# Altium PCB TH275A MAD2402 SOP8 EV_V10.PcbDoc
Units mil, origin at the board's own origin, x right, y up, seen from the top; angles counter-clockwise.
Board outline 1968.5 x 1181.1 mil, 2 copper layers (Top Layer, Bottom Layer); 56 components, 19 nets, 137 pads, 71 vias.
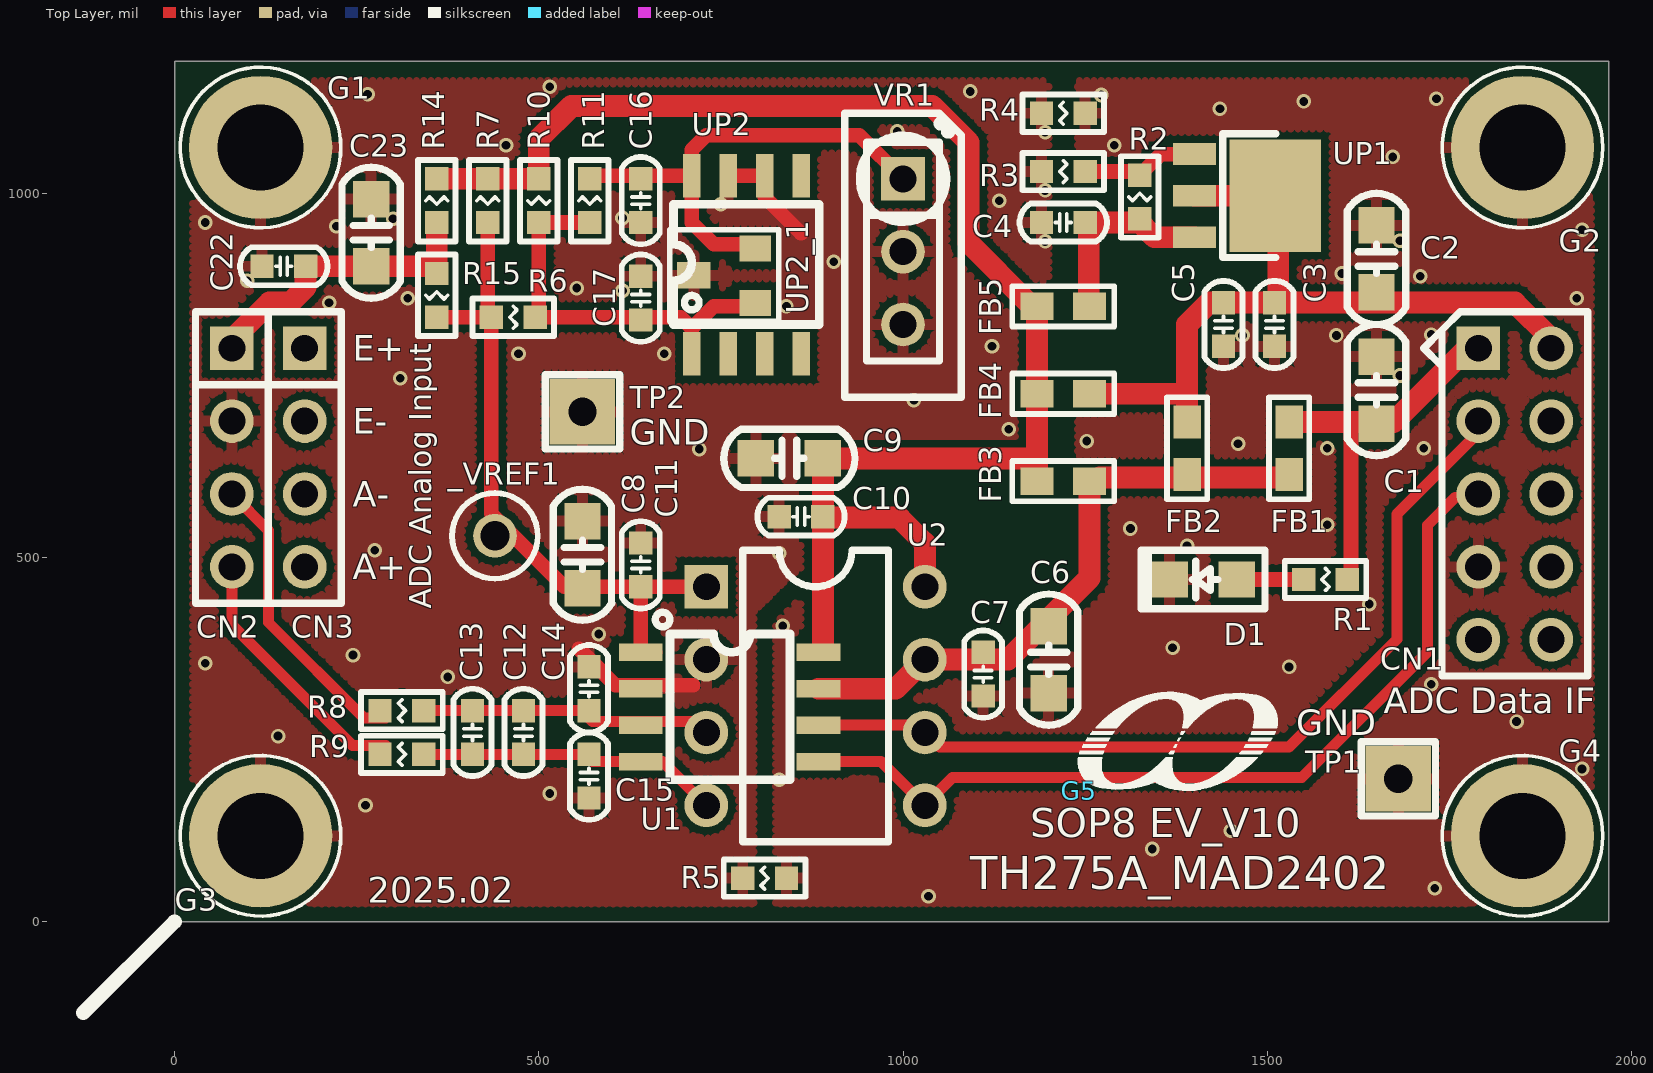
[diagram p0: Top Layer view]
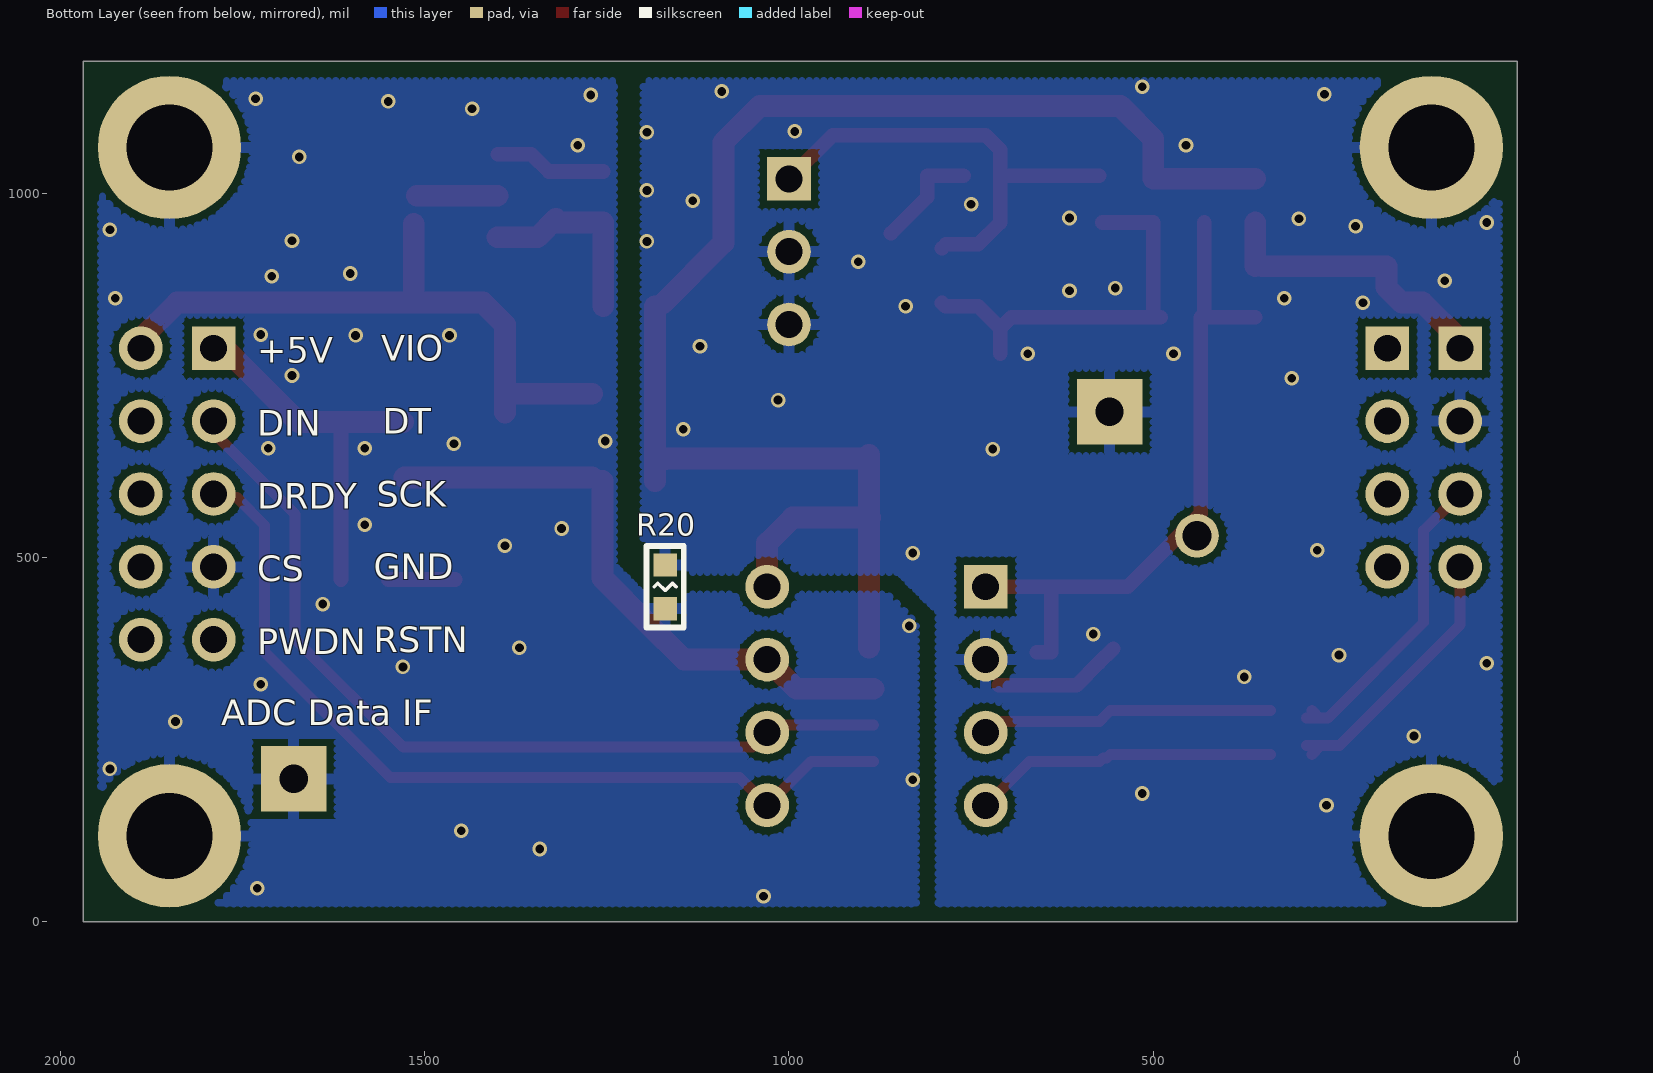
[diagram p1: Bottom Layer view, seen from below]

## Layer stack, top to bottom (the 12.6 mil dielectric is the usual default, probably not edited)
Top Layer: signal copper 1.4
Dielectric: dielectric 12.6, FR-4, Dk 4.8
Bottom Layer: signal copper 1.4

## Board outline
0,0 1968.5,0 1968.5,1181.1 0,1181.1

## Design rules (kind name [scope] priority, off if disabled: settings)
Clearance 10 [All] p1: gap=10
Clearance 7_USB [All] p2 off: gap=7
Clearance 6_CLK [All] p3: gap=6
HoleSize [All] p1: absolutevalues=TRUE maxlimit=500 minlimit=1 maxpercent=80.000 minpercent=20.000
MinimumSolderMaskSliver [All] p1 off: minsoldermaskwidth=10
PolygonConnect via [isvia] p1: connectstyle=Direct reliefconductorwidth=10 reliefentries=4 polygonreliefangle="90 Angle"
PolygonConnect 15 [All] p2: connectstyle=Relief reliefconductorwidth=15 reliefentries=4 polygonreliefangle="90 Angle"
RoomDefinition "TH275A MAD2402 SOP8 EV_V10" [InComponentClass('TH275A MAD2402 SOP8 EV_V10')] p1: confinementstyle=ConfineIn formatcopy=TRUE lockcomponents=FALSE outline -7597.8,-4753.78 -5597.8,-4753.78 -5597.8,-3753.78 -7597.8,-3753.78
RoutingVias 12-20 [All] p1: holewidth=16 width=25 viastyle="Through Hole" minholewidth=12 minwidth=20 maxholewidth=28 maxwidth=50
SilkToSilkClearance [All] p1 off: silktosilkclearance=10
SilkscreenOverComponentPads [All] p1 off: minsilkscreentomaskgap=10
SolderMaskExpansion [All] p1: expansion=4
Width [All] p1: maxlimit=100 minlimit=6 preferedwidth=10
24 further rules are at their usual default settings.

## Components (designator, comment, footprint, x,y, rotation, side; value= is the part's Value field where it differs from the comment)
_VREF1 "TP-COIL" TPH60-COIL 440,530 r0 top
C1 "10uF/10v" C-0805 1650,730 r90 top
C2 "10uF/10v" C-0805 1650,910 r90 top
C3 "0.1uF" C-0603 1510,820 r270 top
C4 "1uF" C-0603 1220,960 r180 top
C5 "1uF" C-0603 1440,820 r270 top
C6 "10uF/10v" C-0805 1200,360 r270 top
C7 "0.1uF" C-0603 1110,340 r270 top
C8 "10uF/10v" C-0805 560,504 r90 top
C9 "10uF/10v" C-0805 844,636.22 r180 top
C10 "0.1uF" C-0603 860,556.22 r180 top
C11 "0.1uF" C-0603 640,490 r90 top
C12 "0.1uF" C-0603 479,260 r270 top
C13 "100pF" C-0603 409,260 r270 top
C14 "0.1uF" C-0603 569,320 r90 top
C15 "0.1uF" C-0603 569,200 r270 top
C16 "0.1uF" C-0603 640,990 r270 top
C17 "1uF" C-0603 640,856.22 r90 top
C22 "0.1uF" C-0603 150,900 r180 top
C23 "10uF/10v" C-0805 270,946 r90 top
CN1 "HEADER5X2-2.54-Male" HD5X2-P2.54 1789.76,787.4 r270 top locked
CN2 "HEADER4-2.54-Male" SIP4-P2.54 78.74,787.4 r270 top locked
CN3 "HEADER4-2.54-Male" SIP4-P2.54 178.74,787.4 r270 top locked
D1 "LED0805-Red" LED-0805 1410,470 r270 top
FB1 "FB" 0603R 1530,650 r270 top
FB2 "FB" 0603R 1390,650 r270 top
FB3 "FB" 0603R 1220,605 r180 top
FB4 "FB" 0603R 1220,725 r180 top
FB5 "FB" 0603R 1220,845 r180 top
G1 "3_0mm_0via" SCREW1-H3.0-R5 118.11,1062.99 r0 top locked
G2 "3_0mm_0via" SCREW1-H3.0-R5 1850.39,1062.99 r0 top locked
G3 "3_0mm_0via" SCREW1-H3.0-R5 118.11,118.11 r0 top locked
G4 "3_0mm_0via" SCREW1-H3.0-R5 1850.39,118.11 r0 top locked
G5 "Logo_Megawin_3_4" MEGAWIN_3.4_LOGO 1242.2,180 r0 top
R1 "3K" R-0603 1580,470 r180 top
R2 "180" R-0603 1325,995 r90 top
R3 "300" R-0603 1220,1030 r180 top
R4 "0" R-0603 1220,1110 r0 top
R5 "0" R-0603 810,60 r0 top
R6 "0" R-0603 465,830 r180 top
R7 "0" R-0603 430,990 r270 top
R8 "1K" R-0603 312.2,290 r0 top
R9 "1K" R-0603 312.2,230 r0 top
R10 "1K" R-0603 500,990 r90 top
R11 "0" R-0603 570,990 r270 top
R14 "0" R-0603 360,990 r270 top
R15 "0" R-0603 360,860 r90 top
R20 "0" R-0603 1170,460 r270 bottom
TP1 "TP-Gold" SIP1-39 1680,196.22 r0 top
TP2 "TP-Gold" SIP1-39 560,700 r0 top
U1 "IC-MAD2402SOP8" SOP8-P1.27-W6.2 640,370 r270 top
U2 "IC-MAD2402-DIP8" DIP8-P2.54-W7.62 730,460 r270 top
UP1 "AP1115B-ADJ" SOT-89-1 1472,996.84 r270 top
UP2 "ICP-TL431B" SOP8-P1.27-W6.2 710,780 r0 top
UP2_1 "TL431A" SOT23 755,887 r90 top
VR1 "VR_20K" SIP3-P2.54-VR 1000,1020 r270 top

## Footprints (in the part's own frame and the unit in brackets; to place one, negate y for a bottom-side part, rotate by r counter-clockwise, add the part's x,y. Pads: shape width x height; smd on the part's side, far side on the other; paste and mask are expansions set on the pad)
0603R [mil]
  rect 45x38 smd: 1(-36,0) 2(36,0)
  silkscreen extent -70,-28 70,28
C-0603 [mil]
  rect 32x32 smd: 1(-30,0) 2(30,0)
  silkscreen extent -60,-26 60,26
C-0805 [mil]
  rect 50x50 smd: 1(-46,0) 2(46,0)
  silkscreen extent -90,-40 90,40
DIP8-P2.54-W7.62 [mil]
  rect 60x60 hole 37: 1(0,0)
  round 60 hole 37: 2(100,0) 3(200,0) 4(300,0) 5(300,300) 6(200,300) 7(100,300) 8(0,300)
  silkscreen extent -50,50 350,250
HD5X2-P2.54 [mil]
  rect 60x60 hole 37: 1(0,0)
  round 60 hole 37: 2(0,100) 3(100,0) 4(100,100) 5(200,0) 6(200,100) 7(300,0) 8(300,100) 9(400,0) 10(400,100)
  silkscreen extent -50,-75 450,150
LED-0805 [mil]
  rect 50x50 smd: 1(0,48) 2(0,-44)
  silkscreen extent -40,-83 40,87
MEGAWIN_3.4_LOGO [mil]
  silkscreen extent -2,0 272,135
R-0603 [mil]
  rect 32x32 smd: 1(-30,0) 2(30,0)
  silkscreen extent -56,-26 56,26
SCREW1-H3.0-R5 [mm]
  round 5 hole 3: 1(0,0)
  silkscreen extent -2.8,-2.8 2.8,2.8
SIP1-39 [mil]
  rect 90x90 hole 39: 1(0,0)
  silkscreen extent -51,-51 51,51
SIP3-P2.54-VR [mil]
  rect 60x60 hole 37: 1(0,0)
  round 60 hole 37: 2(100,0) 3(200,0)
  silkscreen extent -90,-80 300,80
SIP4-P2.54 [mil]
  rect 60x60 hole 37: 1(0,0)
  round 60 hole 37: 2(100,0) 3(200,0) 4(300,0)
  silkscreen extent -50,-50 350,50
SOP8-P1.27-W6.2 [mil]
  rect 24x60 smd: 1(0,0) 2(50,0) 3(100,0) 4(150,0) 5(150,244) 6(100,244) 7(50,244) 8(0,244)
  silkscreen extent -55,20 175,205
SOT23 [mil]
  rect 36x43.31 smd: 1(-37.5,-41.97) 2(37.5,-41.97)
  rect 36x46.06 smd: 3(0.5,41.97)
  silkscreen extent -63,-74 63,75
SOT-89-1 [mil]
  rect 30x59.06 smd: 1(-57,-72) 2(0,-72) 3(57,-72)
  rect 154x126 smd: 4(0,39)
  silkscreen extent -85,-33 85,40
TPH60-COIL [mil]
  round 60 hole 40: 1(0,0)
  silkscreen extent -59,-59 59,59

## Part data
_VREF1: library part TPH60-COIL
C1 C2 C6 C8 C9 C23: library part CAP-POL
C3 C4 C5 C7 C10 C11 C12 C13 C14 C15 C16 C17 C22: library part CAP-NP
CN1: library part HEADER5X2
CN2 CN3: library part HEADER4
D1: library part LED
FB1 FB2 FB3 FB4 FB5: library part FB+DIP-S
G1 G2 G3 G4: library part ScrewPad-1P, "MTG HOLE;ID2.5,OD6.6,NPTH,12 VIA"
G5: library part LOGO-Megawin_3_4
R1 R2 R3 R4 R5 R6 R7 R8 R9 R10 R11 R14 R15 R20: library part R
TP1 TP2: library part TPH-GND
U1: library part IC-MAD710-SOP8
U2: library part IC-MAD710-DIP8
UP1: library part ICP-AP1115B
UP2_1: library part TL431/CYL
VR1: library part HEADER3-VR

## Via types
v1: diameter 20, hole 12, Top Layer to Bottom Layer, tented both sides, 71 vias

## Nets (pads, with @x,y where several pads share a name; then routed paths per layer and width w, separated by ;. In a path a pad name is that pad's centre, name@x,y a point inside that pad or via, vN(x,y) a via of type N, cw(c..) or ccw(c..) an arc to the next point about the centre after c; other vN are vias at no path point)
+5V: C2.1 C3.1 C5.1 CN1.2 FB2.1 FB4.1 UP1.2 UP1.4 | length 989.4
  Top Layer w30: FB4.1@1270,725 1386.8,725 ; FB2.1@1390,699 1390,820 1420,850 C5.1 C3.1 C3.1@1515,850 ; UP1.2 UP1.4 ; UP1.4@1515,957.84 C3.1@1515,850 ; CN1.2@1889.76,800.24 1840,850 C3.1@1515,850
+AVDD_ADC: C9.1 C10.1 FB3.2 FB4.2 FB5.2 R7.1 R10.2 R14.1 U1.8 U2.8 | length 2078.7
  Top Layer w30: R14.1 R7.1 R10.2 500,1075 545,1120 1040,1120 1090,1070 1090,932 FB5.2@1173.5,848.5 ; C10.1@888.43,555 C10.1@890,555 ; U1.8@890,376.22 C10.1@890,555 ; C9.1@890,641.22 C9.1 C10.1 C10.1@890,555 ; C9.1@893.8,636.22 1170,636.22 1170,635 1169,635 ; U2.8 1030,520 995,555 C10.1@890,555 ; FB3.2 1184,635 ; 1184,636.22 FB4.2 FB5.2
+AVDD_LC: C22.1 C23.1 CN2.1 R14.2 R15.2 | length 401.4
  Top Layer w30: CN2.1 78.74,798.74 130,850 158.78,850 180,871.22 C22.1 C23.1 R15.2@350,900 ; R15.2@360,900 R14.2
+DVDD_ADC: C6.1 C7.1 FB1.2 FB2.2 FB3.1 U1.7 U2.7 | length 826
  Top Layer w30: U1.7 990,320 U2.7 1110,360 1144,360 1195,411 1256,472 FB3.1 ; FB3.1@1270,609.84 1390,609.84 FB1.2@1528,609.84
+LDO_ADC: C4.1 FB5.1 R2.1 UP1.3 | length 270.4
  Top Layer w30: FB5.1@1255,845 1255,960 R2.1@1320,960 ; R2.1@1320,965 1345.16,939.84 UP1.3
+VDD: C1.1 CN1.1 FB1.1 R1.1 | length 515.8
  Top Layer w20: R1.1@1615,470 1615,684
  Top Layer w30: FB1.1 1673.36,686 1774.76,787.4 CN1.1
+VREF: _VREF1.1 C8.1 C11.1 R6.2 R7.2 R15.1 U1.1 U2.1 | length 936.4
  Top Layer w20: R15.1 430,830 R7.2 ; R6.2 435,560 452.5,542.5 535,460 560,460 C11.1 ; U1.1@660,370 U1.1 C11.1 ; U2.1@733,443 733,460 U2.1 C11.1
+VREF_REF: C17.1 R6.1 R10.1 R11.2 UP2.1 UP2_1.1 | length 545.5
  Top Layer w20: R6.1@490,830 R6.1 640,830 695,830 710,815 ; R6.1@500,840 R10.1 R11.2 ; UP2.1 710,815 ; UP2_1.1@790,849.5 785.5,845 740,845 710,815
ADC_AIN: C12.1 C13.1 C14.1 R8.2 U1.3 U2.3 | length 403.4
  Top Layer w15: R8.2@339,290 R8.2 C13.1 C12.1 559,290 564,285 574,275 640,275 715,275 U2.3
ADC_AIP: C12.2 C13.2 C15.1 R9.2 U1.4 U2.4 | length 420
  Top Layer w15: R9.2@339,230 R9.2 C13.2 C12.2 559,230 564,225 569,225 574,220 U1.4 670,220 U2.4
ADC_DOUT: CN1.3 U1.6 U2.6 | length 1213.4
  Top Layer w15: U1.6 1020,270 U2.6 1050,240 1530,240 1678,388 1678,560 1789.76,671.76 CN1.3
ADC_I0: CN2.3 R8.1 | length 426.6
  Top Layer w15: CN2.3 128.74,537.4 128.74,411.26 260,280 R8.1@272.2,280 ; R8.1 R8.1@272.2,280 ; R8.1@290,280 R8.1@272.2,280
ADC_I1: CN2.4 R9.1 | length 373.9
  Top Layer w15: CN2.4 78.74,407.4 244.23,241.92 R9.1@290,241.92 ; R9.1@272.2,240 R9.1
ADC_SCK: CN1.5 U1.5 U2.5 | length 1207.8
  Top Layer w15: U1.5 970,220 U2.5 1068,198 1547.4,198 1720,370.6 1720,544.46 1757.94,582.4 CN1.5
GND: C1.2 C2.2 C3.2 C5.2 C6.2 C7.2 CN1.7 D1.2 G2.1 G4.1 R4.2 R5.2 R20.2 TP1.1
  other v1: 1035,35 1730,46.22 1342.2,100 1450,125 830,195 1932.2,210 1842.2,275 1725,326.22 1530,350 1370,376.22 835,406.22 1640,436.22 1390,516.22 1312.2,540 1582.2,545 1582.2,650 1715,650 1460,656.22 1252.2,660 1682.2,750 1466,805 1595,805 1725,806.22 1925,856.22 1710,886.22 1602.2,890 1682.2,935 1932.2,950 1672.2,1050 1290,1066.22 1435,1116.22 1550,1126.22 1732.2,1130 1272.2,1135
GND_A: C4.2 C8.2 C9.2 C10.2 C11.2 C14.2 C15.2 C16.2 C17.2 C22.2 C23.2 CN2.2 G1.1 G3.1 R3.2 R4.1 R5.1 R20.1 TP2.1 U1.2 U2.2 UP2.6 UP2.7 UP2_1.3 VR1.2 VR1.3 | length 327.6
  Top Layer w20: 555,375 574.5,355.5 605,325 640,325 712.2,325 ; UP2.7 UP2.6 810,995 860,945
  other v1: 262.2,160 515,176.22 142.2,255 375,336.22 42.2,355 245,366.22 582.2,395 830,506.22 275,510 720.31,649 1145,676.22 1015,716.22 310,746.22 472.2,780 672.2,780 1122.2,790 840,845 212.2,850 320,856.22 615,866.22 552.2,870 100,880 905,906.22 1195,934 222.2,955 42.2,960 300,965 615,966.22 750,985 1132.2,990 1195,1004 455,1066.22 1195,1084 992.2,1085 265,1136.22 1092.2,1140 515,1146.22
NetC16_1: C16.1 R11.1 UP2.8 UP2_1.2 VR1.1 | length 653.8
  Top Layer w20: R11.1@574,1024 640,1024 UP2.8 ; UP2_1.2@790,924.5 784.5,930 740,930 710,960 UP2.8 ; VR1.1 940,1080 730,1080 710,1060 UP2.8
NetD1_1: D1.1 R1.2 | length 92
  Top Layer w20: D1.1 R1.2
NetR2_2: R2.2 R3.1 UP1.1 | length 154.9
  Top Layer w20: R3.1@1255,1030 1330,1030 1353.84,1053.84 UP1.1
pads on no net: CN1.4 CN1.6 CN1.8 CN1.9 CN1.10 CN3.1 CN3.2 CN3.3 CN3.4 UP2.2 UP2.3 UP2.4 UP2.5

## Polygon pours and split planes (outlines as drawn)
GND_A on Top Layer "Top Layer-No Net" (hatched 90Degree grid 10 track 10, remove dead copper, pour order 1001): 795,25 795,425 850,480 1185,480 1200,495 1200,1155 25,1155 25,25
GND on Top Layer "Top Layer-No Net" (hatched 90Degree grid 10 track 10, remove dead copper, pour order 1000): 1945,25 1945,1155 1240,1155 1240,490 1200,450 865,450 825,410 825,25
GND_A on Bottom Layer "Top Layer-No Net" (hatched 90Degree grid 10 track 10, remove dead copper, pour order 1002): 795,25 795,425 850,480 1185,480 1200,495 1200,1155 25,1155 25,25
GND on Bottom Layer "Top Layer-No Net" (hatched 90Degree grid 10 track 10, remove dead copper, pour order 1003): 1945,25 1945,1155 1240,1155 1240,490 1200,450 865,450 825,410 825,25

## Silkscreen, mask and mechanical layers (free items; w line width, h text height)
Top Overlay:
  lines w20: -125,-125 0,0
  text "E+" at 245,770 h35
  text "E-" at 245,670 h35
  text "GND" at 625,655 h35
  text "A-" at 245,570 h35
  text "A+" at 245,470 h35
  text "ADC Analog Input" at 352.2,430 h30 r90
  text "ADC Data IF" at 1660,286.22 h35
  text "GND" at 1540,256.22 h35
  text "SOP8 EV_V10" at 1175,116.22 h40
  text "TH275A_MAD2402" at 1092.2,45 h45
  text "2025.02" at 265,26.22 h35
Bottom Overlay:
  text "VIO" at 1560,770 h35
  text "+5V" at 1729.76,767.4 h35
  text "DT" at 1557.69,670 h35
  text "DIN" at 1729.76,667.4 h35
  text "SCK" at 1565.85,569.99 h35
  text "DRDY" at 1729.76,567.4 h35
  text "GND" at 1570,470 h35
  text "CS" at 1729.76,467.4 h35
  text "RSTN" at 1570,370 h35
  text "PWDN" at 1729.76,367.4 h35
  text "ADC Data IF" at 1779.47,270.09 h35
Mechanical 1:
  the board outline again, w20

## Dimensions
0,0 to 0,1181.1 on Top Overlay
0,0 to 1968.5,0 on Top Overlay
